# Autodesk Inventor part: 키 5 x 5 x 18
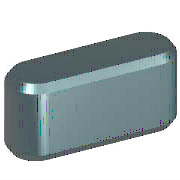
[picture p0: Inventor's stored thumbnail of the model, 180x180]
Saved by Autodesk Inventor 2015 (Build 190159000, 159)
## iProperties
IsCustomPart: 1
Created: 2012-02
Part Number: 키 5 x 5 x 18
Material: 강철, 연강
Description: 키 및 해당 키홈
Document SubType Name: Modeling
Standard: KS B 1311
Designer: mduedu
Standards Organization: KS
Language: ko-KR
Size Designation: 5 x 5 x 18
Categories: <MemberInstance><Categories><Category DisplayName="샤프트 부품" InternalName="7f7aeb1f-a693-4053-b835-cee3144e0d98" Mnemonic="SHFT"><Category DisplayName="키" Interna
Density: 7.86 g/cm^3
Appearance: 금색
Mass: 3.27476 g
Surface Area: 3.57848 cm^2
Volume: 0.416636 cm^3
Author: mduedu
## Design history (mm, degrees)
workplane "Work Plane1"
workplane "Work Plane2"
sketch "스케치1"
  geometry: L1 (2.5, 2.5)-(15.5, 2.5); L2 (15.5, -2.5)-(2.5, -2.5); L3 (0, 9.4)-(0, -7.4) reference; L4 (-5, 0)-(30, 0) reference; L5 (18, 0)-(18, 7); A1 r 2.5 centre (2.5, 0) between (2.5, 2.5) and (2.5, -2.5); A2 r 2.5 centre (15.5, 0) between (15.5, -2.5) and (15.5, 2.5)
  constraints: 6 end point, 5 point on circle, 4 tangent, 3 point on line, 2 centre point, 1 horizontal, 1 parallel, 1 perpendicular
  dimensions: "d0" = 2.5 radius of A1 (= 0.5 x PB); "d13" = 2.5 radius of A2 (= 0.5 x PB); "d14" = 18 distance between parallel lines of L5 L3 (= NLG)
extrude "본체1" new body sketch "스케치1" taper "d3" = 0 deg; stored distance "d4" = 10
workplane "Work Plane3"
body "Solid1"
chamfer "모따기1" distance "d8" = 0.4 (= PHH); stored, may be unused: second distance "d9" = 0.4 (= PHH), angle "d15" = 45 deg
other parameters: "d1" = -3 (= -PNT), "d2" = 2 (= PH - PNT), "NLG" = 18 [user parameter; used in 3 equation terms], "PB" = 5 [user parameter; used in 2 equation terms], "PNT" = 3 [user parameter; used in 2 equation terms], "PH" = 5 [user parameter; used in 1 equation term], "PHH" = 0.4 [user parameter; used in 2 equation terms], "d10" = 0, "d16" = 0, "d17" = 0, "d18" = 0, "WDMIN" = 12 [user parameter], "PLB2" = 18 (= NLG) [user parameter], "WDMAX" = 17 [user parameter], "PLB1" = 18 (= NLG) [user parameter], "RR" = 0.16 [user parameter], "PUEB" = 2.3 [user parameter]
